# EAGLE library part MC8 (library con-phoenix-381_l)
Mini-Combicon 3.81mm horizontal 8-polig (ohne Gegenstecker)
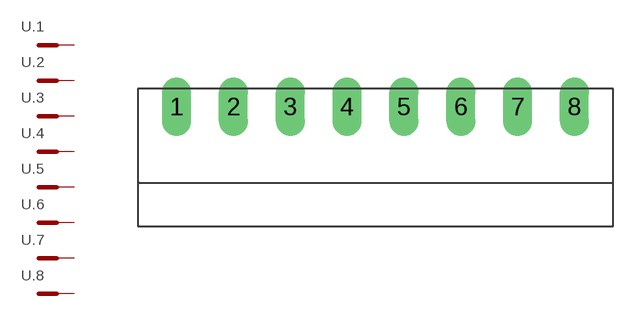
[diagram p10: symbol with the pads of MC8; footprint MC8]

Designator prefix -; gates .1=MCST .2=MCST .3=MCST .4=MCST .5=MCST .6=MCST .7=MCST .8=MCST

## MC8  [MC8]
1  .1:SK  pas
2  .2:SK  pas
3  .3:SK  pas
4  .4:SK  pas
5  .5:SK  pas
6  .6:SK  pas
7  .7:SK  pas
8  .8:SK  pas

## Footprint MC8 (pad centres in mm)
Mini-Combicon 3.81mm horizontal 8-polig (ohne Gegenstecker)
drill 1.3 long: 1 -13.335,0; 2 -9.525,0; 3 -5.715,0; 4 -1.905,0; 5 1.905,0; 6 5.715,0; 7 9.525,0; 8 13.335,0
